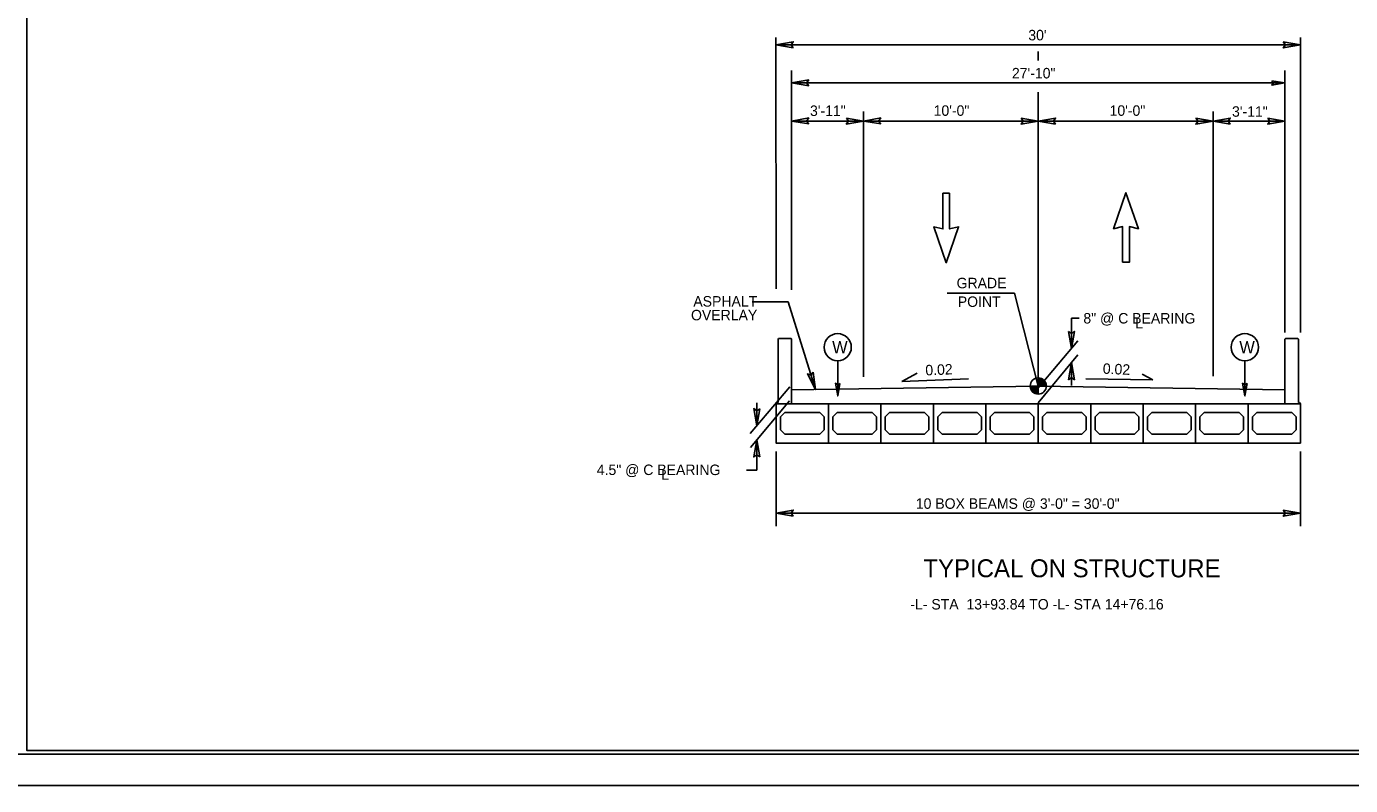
# Model space of a CAD drawing. Extents: x 1542177 to 1542464, y 45134 to 45344.
# Drawn here: x 1542239.3 to 1542315.1, y 45134.4 to 45177.9 of the extents above; entities that cross this region are included whole.
import ezdxf

# ---------------------------------------------------------------- set-up
doc = ezdxf.new("R2010")
doc.units = 0
for name, color, linetype in [('Default', 7, 'Continuous'), ('Old_Level_1', 7, 'Continuous'), ('Old_Level_11', 7, 'Continuous'), ('Old_Level_3', 7, 'Continuous'), ('Sheet Cutting Line CELL', 7, 'Continuous'), ('Sheet Plot Border Inside CELL', 7, 'Continuous'), ('Sheet Plot Border Outside CELL', 7, 'Continuous'), ('Sheet Typical CELL', 7, 'Continuous'), ('Typical ID Circle CELL', 7, 'Continuous')]:
    doc.layers.add(name, color=color, linetype=linetype)

# ---------------------------------------------------------------- blocks, each defined once
blk = doc.blocks.new('ARROW3_1')
at = {"layer": 'Default'}
blk.add_lwpolyline([(-0.027, -0.555), (-0.027, -0.27), (-0.099, -0.287), (0, 0), (0.099, -0.287), (0.027, -0.27), (0.027, -0.555), (-0.027, -0.555)], dxfattribs=at)
blk = doc.blocks.new('CIR')
at = {"layer": 'Default'}
blk.add_line((0, 1.914), (0, 0), dxfattribs=at)
blk.add_lwpolyline([(0.118, 0.686), (0, 0), (-0.122, 0.69), (0, 0.602)], close=True, dxfattribs=at)
blk.add_circle((0, 2.654), 0.741, dxfattribs=at)

msp = doc.modelspace()

# ---------------------------------------------------------------- linework, layer by layer
at = {"layer": 'Default'}
for p, q in [((1542297.238, 45176.454), (1542297.238, 45175.932)), ((1542297.238, 45174.13), (1542297.237, 45157.426)), ((1542297.254, 45157.22), (1542299.503, 45159.885)), ((1542297.233, 45156.337), (1542299.505, 45159.098)), ((1542289.43, 45157.567), (1542290.304, 45158.049)), ((1542289.43, 45157.567), (1542293.246, 45157.719)), ((1542299.967, 45157.723), (1542303.785, 45157.663)), ((1542303.785, 45157.663), (1542303.172, 45157.982)), ((1542283.023, 45157.267), (1542280.76, 45154.585)), ((1542283.011, 45156.463), (1542280.762, 45153.797))]:
    msp.add_line(p, q, dxfattribs=at)
for points in [[(1542283.212, 45176.666), (1542282.23, 45176.835), (1542283.217, 45177.01), (1542283.092, 45176.835)], [(1542311.258, 45177.001), (1542312.24, 45176.832), (1542311.253, 45176.658), (1542311.378, 45176.832)], [(1542284.102, 45174.484), (1542283.121, 45174.653), (1542284.108, 45174.828), (1542283.982, 45174.653)], [(1542284.103, 45172.302), (1542283.121, 45172.471), (1542284.108, 45172.646), (1542283.983, 45172.471)], [(1542286.256, 45172.64), (1542287.238, 45172.471), (1542286.25, 45172.297), (1542286.376, 45172.471)], [(1542288.22, 45172.302), (1542287.238, 45172.471), (1542288.225, 45172.645), (1542288.1, 45172.471)], [(1542296.256, 45172.639), (1542297.238, 45172.47), (1542296.25, 45172.296), (1542296.376, 45172.47)], [(1542298.22, 45172.301), (1542297.238, 45172.47), (1542298.225, 45172.644), (1542298.1, 45172.47)], [(1542306.256, 45172.638), (1542307.238, 45172.469), (1542306.251, 45172.295), (1542306.376, 45172.469)], [(1542308.22, 45172.3), (1542307.238, 45172.469), (1542308.225, 45172.643), (1542308.1, 45172.469)], [(1542310.367, 45172.638), (1542311.349, 45172.469), (1542310.362, 45172.294), (1542310.487, 45172.469)], [(1542298.965, 45160.431), (1542299.134, 45159.449), (1542299.309, 45160.436), (1542299.134, 45160.311)], [(1542298.962, 45157.672), (1542299.131, 45158.654), (1542299.305, 45157.667), (1542299.131, 45157.792)], [(1542284.355, 45158.097), (1542284.484, 45157.109), (1542284.025, 45158.001), (1542284.229, 45157.932)], [(1542281.303, 45156.01), (1542281.134, 45155.029), (1542280.96, 45156.016), (1542281.134, 45155.89)], [(1542281.3, 45153.252), (1542281.131, 45154.234), (1542280.956, 45153.247), (1542281.131, 45153.372)], [(1542283.213, 45149.861), (1542282.231, 45150.031), (1542283.219, 45150.205), (1542283.093, 45150.031)], [(1542311.256, 45150.197), (1542312.238, 45150.028), (1542311.251, 45149.853), (1542311.376, 45150.028)]]:
    msp.add_lwpolyline(points, close=True, dxfattribs=at)
at = {"layer": 'Old_Level_1'}
for p, q in [((1542282.23, 45177.26), (1542282.231, 45162.869)), ((1542312.24, 45177.26), (1542312.239, 45160.363)), ((1542282.23, 45176.835), (1542312.24, 45176.832)), ((1542283.12, 45175.358), (1542283.121, 45162.82)), ((1542311.349, 45175.358), (1542311.348, 45160.363)), ((1542283.121, 45174.653), (1542311.349, 45174.65)), ((1542287.238, 45173.02), (1542287.239, 45157.841)), ((1542307.238, 45173.02), (1542307.237, 45157.87)), ((1542283.121, 45172.471), (1542287.238, 45172.471)), ((1542287.238, 45172.471), (1542297.238, 45172.47)), ((1542297.238, 45172.47), (1542307.238, 45172.469)), ((1542307.238, 45172.469), (1542311.349, 45172.469)), ((1542292.025, 45162.625), (1542295.883, 45162.625)), ((1542297.237, 45157.309), (1542295.883, 45162.625)), ((1542282.374, 45160.019), (1542282.345, 45159.991)), ((1542282.345, 45159.991), (1542282.345, 45156.356)), ((1542283.093, 45160.019), (1542282.374, 45160.019)), ((1542283.093, 45160.019), (1542283.122, 45159.991)), ((1542283.122, 45159.991), (1542283.121, 45156.298)), ((1542311.377, 45160.019), (1542311.348, 45159.991)), ((1542311.348, 45159.991), (1542311.349, 45156.298)), ((1542311.377, 45160.019), (1542312.096, 45160.019)), ((1542312.096, 45160.019), (1542312.125, 45159.991)), ((1542312.125, 45159.991), (1542312.124, 45156.356)), ((1542297.236, 45157.773), (1542297.237, 45157.309)), ((1542297.237, 45157.309), (1542297.236, 45157.773)), ((1542297.237, 45157.309), (1542283.121, 45157.089)), ((1542296.774, 45157.309), (1542297.237, 45157.309)), ((1542297.7, 45157.31), (1542297.237, 45157.309)), ((1542297.237, 45157.309), (1542297.237, 45156.846)), ((1542297.237, 45157.309), (1542311.348, 45157.089)), ((1542282.288, 45156.356), (1542282.231, 45156.298)), ((1542282.345, 45156.356), (1542282.288, 45156.356)), ((1542312.124, 45156.356), (1542312.181, 45156.356)), ((1542312.181, 45156.356), (1542312.239, 45156.298)), ((1542282.481, 45155.548), (1542282.731, 45155.798)), ((1542282.481, 45154.798), (1542282.481, 45155.548)), ((1542282.731, 45155.798), (1542284.732, 45155.798)), ((1542284.732, 45155.798), (1542284.982, 45155.548)), ((1542284.982, 45155.548), (1542284.982, 45154.798)), ((1542285.482, 45155.548), (1542285.732, 45155.798)), ((1542285.482, 45154.798), (1542285.482, 45155.548)), ((1542285.732, 45155.798), (1542287.733, 45155.798)), ((1542287.733, 45155.798), (1542287.983, 45155.548)), ((1542287.983, 45155.548), (1542287.983, 45154.798)), ((1542288.483, 45155.548), (1542288.733, 45155.798)), ((1542288.483, 45154.798), (1542288.483, 45155.548)), ((1542288.733, 45155.798), (1542290.733, 45155.798)), ((1542290.733, 45155.798), (1542290.983, 45155.548)), ((1542290.983, 45155.548), (1542290.983, 45154.798)), ((1542291.483, 45155.548), (1542291.734, 45155.798)), ((1542291.483, 45154.798), (1542291.483, 45155.548)), ((1542291.734, 45155.798), (1542293.734, 45155.798)), ((1542293.734, 45155.798), (1542293.984, 45155.548)), ((1542293.984, 45155.548), (1542293.984, 45154.798)), ((1542294.484, 45155.548), (1542294.734, 45155.798)), ((1542294.484, 45154.798), (1542294.484, 45155.548)), ((1542294.734, 45155.798), (1542296.735, 45155.798)), ((1542296.735, 45155.798), (1542296.985, 45155.548)), ((1542296.985, 45155.548), (1542296.985, 45154.798)), ((1542297.485, 45155.548), (1542297.735, 45155.798)), ((1542297.485, 45154.798), (1542297.485, 45155.548)), ((1542297.735, 45155.798), (1542299.735, 45155.798)), ((1542299.735, 45155.798), (1542299.986, 45155.548)), ((1542299.986, 45155.548), (1542299.986, 45154.798)), ((1542300.486, 45155.548), (1542300.736, 45155.798)), ((1542300.486, 45154.798), (1542300.486, 45155.548)), ((1542300.736, 45155.798), (1542302.736, 45155.798)), ((1542302.736, 45155.798), (1542302.986, 45155.548)), ((1542302.986, 45155.548), (1542302.986, 45154.798)), ((1542303.486, 45155.548), (1542303.736, 45155.798)), ((1542303.486, 45154.798), (1542303.486, 45155.548)), ((1542303.736, 45155.798), (1542305.737, 45155.798)), ((1542305.737, 45155.798), (1542305.987, 45155.548)), ((1542305.987, 45155.548), (1542305.987, 45154.798)), ((1542306.487, 45155.548), (1542306.737, 45155.798)), ((1542306.487, 45154.798), (1542306.487, 45155.548)), ((1542306.737, 45155.798), (1542308.738, 45155.798)), ((1542308.738, 45155.798), (1542308.988, 45155.548)), ((1542308.988, 45155.548), (1542308.988, 45154.798)), ((1542309.488, 45155.548), (1542309.738, 45155.798)), ((1542309.488, 45154.798), (1542309.488, 45155.548)), ((1542309.738, 45155.798), (1542311.738, 45155.798)), ((1542311.738, 45155.798), (1542311.988, 45155.548)), ((1542311.988, 45155.548), (1542311.988, 45154.798)), ((1542282.731, 45154.548), (1542282.481, 45154.798)), ((1542284.732, 45154.548), (1542282.731, 45154.548)), ((1542284.982, 45154.798), (1542284.732, 45154.548)), ((1542285.732, 45154.548), (1542285.482, 45154.798)), ((1542287.733, 45154.548), (1542285.732, 45154.548)), ((1542287.983, 45154.798), (1542287.733, 45154.548)), ((1542288.733, 45154.548), (1542288.483, 45154.798)), ((1542290.733, 45154.548), (1542288.733, 45154.548)), ((1542290.983, 45154.798), (1542290.733, 45154.548)), ((1542291.734, 45154.548), (1542291.483, 45154.798)), ((1542293.734, 45154.548), (1542291.734, 45154.548)), ((1542293.984, 45154.798), (1542293.734, 45154.548)), ((1542294.734, 45154.548), (1542294.484, 45154.798)), ((1542296.735, 45154.548), (1542294.734, 45154.548)), ((1542296.985, 45154.798), (1542296.735, 45154.548)), ((1542297.735, 45154.548), (1542297.485, 45154.798)), ((1542299.735, 45154.548), (1542297.735, 45154.548)), ((1542299.986, 45154.798), (1542299.735, 45154.548)), ((1542300.736, 45154.548), (1542300.486, 45154.798)), ((1542302.736, 45154.548), (1542300.736, 45154.548)), ((1542302.986, 45154.798), (1542302.736, 45154.548)), ((1542303.736, 45154.548), (1542303.486, 45154.798)), ((1542305.737, 45154.548), (1542303.736, 45154.548)), ((1542305.987, 45154.798), (1542305.737, 45154.548)), ((1542306.737, 45154.548), (1542306.487, 45154.798)), ((1542308.738, 45154.548), (1542306.737, 45154.548)), ((1542308.988, 45154.798), (1542308.738, 45154.548)), ((1542309.738, 45154.548), (1542309.488, 45154.798)), ((1542311.738, 45154.548), (1542309.738, 45154.548)), ((1542311.988, 45154.798), (1542311.738, 45154.548)), ((1542282.231, 45153.565), (1542282.232, 45149.292)), ((1542312.238, 45153.563), (1542312.238, 45149.29)), ((1542282.231, 45150.031), (1542312.238, 45150.028))]:
    msp.add_line(p, q, dxfattribs=at)
for points in [[(1542297.244, 45157.309), (1542297.243, 45157.773), (1542297.243, 45157.773)], [(1542297.253, 45157.309), (1542297.252, 45157.773)], [(1542297.262, 45157.309), (1542297.261, 45157.772)], [(1542297.271, 45157.309), (1542297.271, 45157.772)], [(1542297.28, 45157.309), (1542297.28, 45157.771)], [(1542297.29, 45157.309), (1542297.289, 45157.77)], [(1542297.299, 45157.309), (1542297.298, 45157.769)], [(1542297.308, 45157.31), (1542297.308, 45157.767)], [(1542297.318, 45157.309), (1542297.317, 45157.766)], [(1542297.327, 45157.31), (1542297.326, 45157.764)], [(1542297.336, 45157.31), (1542297.335, 45157.762)], [(1542297.345, 45157.31), (1542297.345, 45157.76)], [(1542297.355, 45157.31), (1542297.354, 45157.758)], [(1542297.364, 45157.31), (1542297.363, 45157.755)], [(1542297.373, 45157.31), (1542297.373, 45157.753)], [(1542297.382, 45157.31), (1542297.382, 45157.75)], [(1542297.392, 45157.31), (1542297.391, 45157.746)], [(1542297.401, 45157.31), (1542297.4, 45157.743)], [(1542297.41, 45157.31), (1542297.41, 45157.739)], [(1542297.42, 45157.31), (1542297.419, 45157.736)], [(1542297.429, 45157.31), (1542297.428, 45157.731)], [(1542297.438, 45157.31), (1542297.437, 45157.727)], [(1542297.447, 45157.31), (1542297.447, 45157.723)], [(1542297.457, 45157.31), (1542297.456, 45157.718)], [(1542297.466, 45157.31), (1542297.465, 45157.713)], [(1542297.475, 45157.31), (1542297.475, 45157.707)], [(1542297.484, 45157.31), (1542297.484, 45157.702)], [(1542297.494, 45157.31), (1542297.493, 45157.696)], [(1542297.503, 45157.31), (1542297.502, 45157.689)], [(1542297.512, 45157.31), (1542297.512, 45157.682)], [(1542297.522, 45157.31), (1542297.521, 45157.676)], [(1542297.531, 45157.31), (1542297.53, 45157.668)], [(1542297.54, 45157.31), (1542297.54, 45157.66)], [(1542297.549, 45157.31), (1542297.549, 45157.652)], [(1542297.558, 45157.31), (1542297.558, 45157.643)], [(1542297.568, 45157.31), (1542297.567, 45157.634)], [(1542297.577, 45157.31), (1542297.576, 45157.625)], [(1542297.586, 45157.31), (1542297.586, 45157.614)], [(1542297.596, 45157.31), (1542297.595, 45157.603)], [(1542297.605, 45157.31), (1542297.604, 45157.591)], [(1542297.614, 45157.31), (1542297.614, 45157.579)], [(1542297.623, 45157.31), (1542297.623, 45157.565)], [(1542297.633, 45157.31), (1542297.632, 45157.551)], [(1542297.642, 45157.31), (1542297.641, 45157.535)], [(1542297.651, 45157.31), (1542297.651, 45157.518)], [(1542297.66, 45157.31), (1542297.66, 45157.498)], [(1542297.67, 45157.31), (1542297.669, 45157.476)], [(1542296.778, 45157.243), (1542296.778, 45157.309)], [(1542296.788, 45157.196), (1542296.787, 45157.309)], [(1542296.797, 45157.164), (1542296.797, 45157.309)], [(1542296.806, 45157.139), (1542296.806, 45157.309)], [(1542296.815, 45157.117), (1542296.816, 45157.309)], [(1542296.825, 45157.097), (1542296.825, 45157.309)], [(1542296.834, 45157.08), (1542296.834, 45157.309)], [(1542296.844, 45157.065), (1542296.843, 45157.309)], [(1542296.853, 45157.05), (1542296.852, 45157.309)], [(1542296.862, 45157.037), (1542296.862, 45157.309)], [(1542296.871, 45157.025), (1542296.871, 45157.309)], [(1542296.88, 45157.014), (1542296.88, 45157.309)], [(1542296.89, 45157.002), (1542296.89, 45157.309)], [(1542296.899, 45156.992), (1542296.899, 45157.309)], [(1542296.909, 45156.983), (1542296.908, 45157.309)], [(1542296.918, 45156.974), (1542296.917, 45157.309)], [(1542296.927, 45156.965), (1542296.927, 45157.309)], [(1542296.936, 45156.957), (1542296.936, 45157.309)], [(1542296.945, 45156.949), (1542296.945, 45157.309)], [(1542296.955, 45156.942), (1542296.954, 45157.309)], [(1542296.964, 45156.935), (1542296.964, 45157.309)], [(1542296.973, 45156.928), (1542296.973, 45157.309)], [(1542296.983, 45156.922), (1542296.982, 45157.309)], [(1542296.992, 45156.916), (1542296.992, 45157.309)], [(1542297.001, 45156.911), (1542297.001, 45157.309)], [(1542297.01, 45156.905), (1542297.01, 45157.309)], [(1542297.02, 45156.9), (1542297.019, 45157.309)], [(1542297.029, 45156.895), (1542297.028, 45157.309)], [(1542297.038, 45156.891), (1542297.038, 45157.309)], [(1542297.048, 45156.887), (1542297.047, 45157.309)], [(1542297.057, 45156.882), (1542297.056, 45157.309)], [(1542297.066, 45156.879), (1542297.066, 45157.309)], [(1542297.075, 45156.875), (1542297.075, 45157.309)], [(1542297.084, 45156.872), (1542297.084, 45157.309)], [(1542297.094, 45156.869), (1542297.093, 45157.309)], [(1542297.103, 45156.866), (1542297.103, 45157.309)], [(1542297.112, 45156.863), (1542297.112, 45157.309)], [(1542297.122, 45156.861), (1542297.121, 45157.309)], [(1542297.131, 45156.859), (1542297.13, 45157.309)], [(1542297.14, 45156.856), (1542297.14, 45157.309)], [(1542297.15, 45156.855), (1542297.149, 45157.309)], [(1542297.159, 45156.853), (1542297.158, 45157.309)], [(1542297.168, 45156.851), (1542297.168, 45157.309)], [(1542297.177, 45156.85), (1542297.177, 45157.309)], [(1542297.187, 45156.849), (1542297.186, 45157.309)], [(1542297.196, 45156.848), (1542297.195, 45157.309)], [(1542297.205, 45156.847), (1542297.205, 45157.309)], [(1542297.215, 45156.847), (1542297.214, 45157.309)], [(1542297.224, 45156.847), (1542297.223, 45157.309)], [(1542297.233, 45156.846), (1542297.233, 45156.846), (1542297.232, 45157.309)], [(1542297.679, 45157.31), (1542297.679, 45157.449)], [(1542297.688, 45157.31), (1542297.688, 45157.415)], [(1542297.698, 45157.31), (1542297.697, 45157.361)]]:
    msp.add_lwpolyline(points, dxfattribs=at)
for points in [[(1542282.231, 45156.298), (1542285.232, 45156.298), (1542285.232, 45154.048), (1542282.231, 45154.048)], [(1542285.232, 45156.298), (1542288.233, 45156.298), (1542288.233, 45154.048), (1542285.232, 45154.048)], [(1542288.233, 45156.298), (1542291.233, 45156.298), (1542291.233, 45154.048), (1542288.233, 45154.048)], [(1542291.233, 45156.298), (1542294.234, 45156.298), (1542294.234, 45154.048), (1542291.233, 45154.048)], [(1542294.234, 45156.298), (1542297.235, 45156.298), (1542297.235, 45154.048), (1542294.234, 45154.048)], [(1542297.235, 45156.298), (1542300.236, 45156.298), (1542300.236, 45154.048), (1542297.235, 45154.048)], [(1542300.236, 45156.298), (1542303.236, 45156.298), (1542303.236, 45154.048), (1542300.236, 45154.048)], [(1542303.236, 45156.298), (1542306.237, 45156.298), (1542306.237, 45154.048), (1542303.236, 45154.048)], [(1542306.237, 45156.298), (1542309.238, 45156.298), (1542309.238, 45154.048), (1542306.237, 45154.048)], [(1542309.238, 45156.298), (1542312.239, 45156.298), (1542312.239, 45154.048), (1542309.238, 45154.048)]]:
    msp.add_lwpolyline(points, close=True, dxfattribs=at)
msp.add_circle((1542297.237, 45157.31), 0.463, dxfattribs=at)
for start, end in [(0.07945, 90.07945), (180.07945, 270.07945)]:
    msp.add_arc((1542297.237, 45157.31), 0.463, start, end, dxfattribs=at)
at = {"layer": 'Old_Level_11'}
msp.add_lwpolyline([(1542310.609, 45174.771), (1542311.349, 45174.65), (1542310.609, 45174.516), (1542310.704, 45174.65)], close=True, dxfattribs=at)
at = {"layer": 'Sheet Cutting Line CELL'}
msp.add_line((1542226.007, 45134.448), (1542360.727, 45134.448), dxfattribs=at)
at = {"layer": 'Sheet Plot Border Inside CELL'}
msp.add_lwpolyline([(1542360.367, 45220.652), (1542227.047, 45220.652), (1542227.047, 45136.244), (1542360.367, 45136.244)], close=True, dxfattribs=at)
at = {"layer": 'Sheet Plot Border Outside CELL'}
msp.add_lwpolyline([(1542360.727, 45222.448), (1542226.007, 45222.448), (1542226.007, 45134.448), (1542360.727, 45134.448)], close=True, dxfattribs=at)
at = {"layer": 'Sheet Typical CELL'}
msp.add_line((1542239.367, 45136.448), (1542239.367, 45136.448), dxfattribs=at)
msp.add_line((1542239.367, 45136.448), (1542239.367, 45136.448), dxfattribs=at)
msp.add_line((1542239.367, 45136.448), (1542239.367, 45136.448), dxfattribs=at)
msp.add_line((1542239.367, 45136.448), (1542239.367, 45136.448), dxfattribs=at)
msp.add_line((1542239.367, 45136.448), (1542239.367, 45136.448), dxfattribs=at)
msp.add_line((1542239.367, 45136.448), (1542239.367, 45136.448), dxfattribs=at)
msp.add_lwpolyline([(1542359.367, 45220.448), (1542239.367, 45220.448), (1542239.367, 45136.448), (1542359.367, 45136.448)], close=True, dxfattribs=at)
msp.add_lwpolyline([(1542242.367, 45136.448), (1542242.367, 45136.448)], dxfattribs=at)
at = {"layer": 'Typical ID Circle CELL'}
for p, q in [((1542282.934, 45162.123), (1542280.859, 45162.123)), ((1542284.487, 45157.11), (1542282.934, 45162.123)), ((1542299.131, 45159.449), (1542299.131, 45161.188)), ((1542299.131, 45161.188), (1542299.572, 45161.188)), ((1542299.131, 45157.345), (1542299.131, 45158.654)), ((1542281.134, 45156.337), (1542281.134, 45155.029)), ((1542281.134, 45154.234), (1542281.134, 45152.495)), ((1542281.134, 45152.495), (1542280.535, 45152.495))]:
    msp.add_line(p, q, dxfattribs=at)

# ---------------------------------------------------------------- block references
at = {"layer": 'Default', "xscale": 7.158409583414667, "yscale": 7.158409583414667, "rotation": 180}
msp.add_blockref('ARROW3_1', (1542291.97, 45164.366), dxfattribs=at)
at = {"layer": 'Default'}
for name, p, xscale, yscale in [('ARROW3_1', (1542302.254, 45168.363), 7.158409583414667, 7.158409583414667), ('CIR', (1542285.76, 45156.74), 1.0498642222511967, 1.0498642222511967), ('CIR', (1542309.057, 45156.74), 1.0498642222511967, 1.0498642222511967)]:
    msp.add_blockref(name, p, dxfattribs=dict(at, xscale=xscale, yscale=yscale))

# ---------------------------------------------------------------- texts
for s, height, p in [("30'", 0.6, (1542296.666, 45177.087)), ('27\'-10"', 0.6, (1542295.73, 45174.91)), ('W', 0.698, (1542285.445, 45159.178)), ('W', 0.698, (1542308.743, 45159.178)), ('10 BOX BEAMS @ 3\'-0" = 30\'-0"', 0.6, (1542290.23, 45150.282)), ('-L- STA  13+93.84 TO -L- STA 14+76.16', 0.6, (1542289.917, 45144.521))]:
    msp.add_text(s, height=height, dxfattribs=at).set_placement(p)
for s, rotation, p in [('3\'-11"', 359.99657, (1542284.176, 45172.761)), ('10\'-0"', 359.99657, (1542291.25, 45172.77)), ('10\'-0"', 359.99657, (1542301.317, 45172.77)), ('3\'-11"', 359.99657, (1542308.323, 45172.716)), ('GRADE', 360, (1542292.564, 45162.901)), ('ASPHALT', 0.02708, (1542277.5, 45161.854)), ('POINT', 360, (1542292.632, 45161.834)), ('OVERLAY', 0.02708, (1542277.368, 45161.067)), ('8" @ C BEARING', 359.97292, (1542299.818, 45160.887)), ('L', 359.97292, (1542302.789, 45160.606)), ('0.02', 2.51455, (1542290.789, 45157.91)), ('0.02', 357.43154, (1542300.919, 45158.013)), ('4.5" @ C BEARING', 359.97292, (1542271.976, 45152.216)), ('L', 359.97292, (1542275.665, 45151.944))]:
    msp.add_text(s, height=0.6, rotation=rotation, dxfattribs=at).set_placement(p)
at = {"layer": 'Old_Level_3'}
msp.add_text('TYPICAL ON STRUCTURE', height=1.02627, rotation=359.97292, dxfattribs=at).set_placement((1542290.662, 45146.369))

doc.saveas('drawing.dxf')
